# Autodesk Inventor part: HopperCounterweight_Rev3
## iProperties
Created: 2009-01
Part Number: HopperCounterweight_Rev3
Document SubType Name: Modeling
Designer: claivier
Norme de conversion: STEP AP214IS
Nom du fichier: HopperCounterweight_Rev3.STEP
Préprocesseur: SolidWorks 2008
Postprocesseur: Build: 344a, Release: 11 SP2 - Date: Fri 08/18/2006
Unités envoyées: INCHES
Incertitude: 1e-05
Author: claivier
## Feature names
1. Base1
